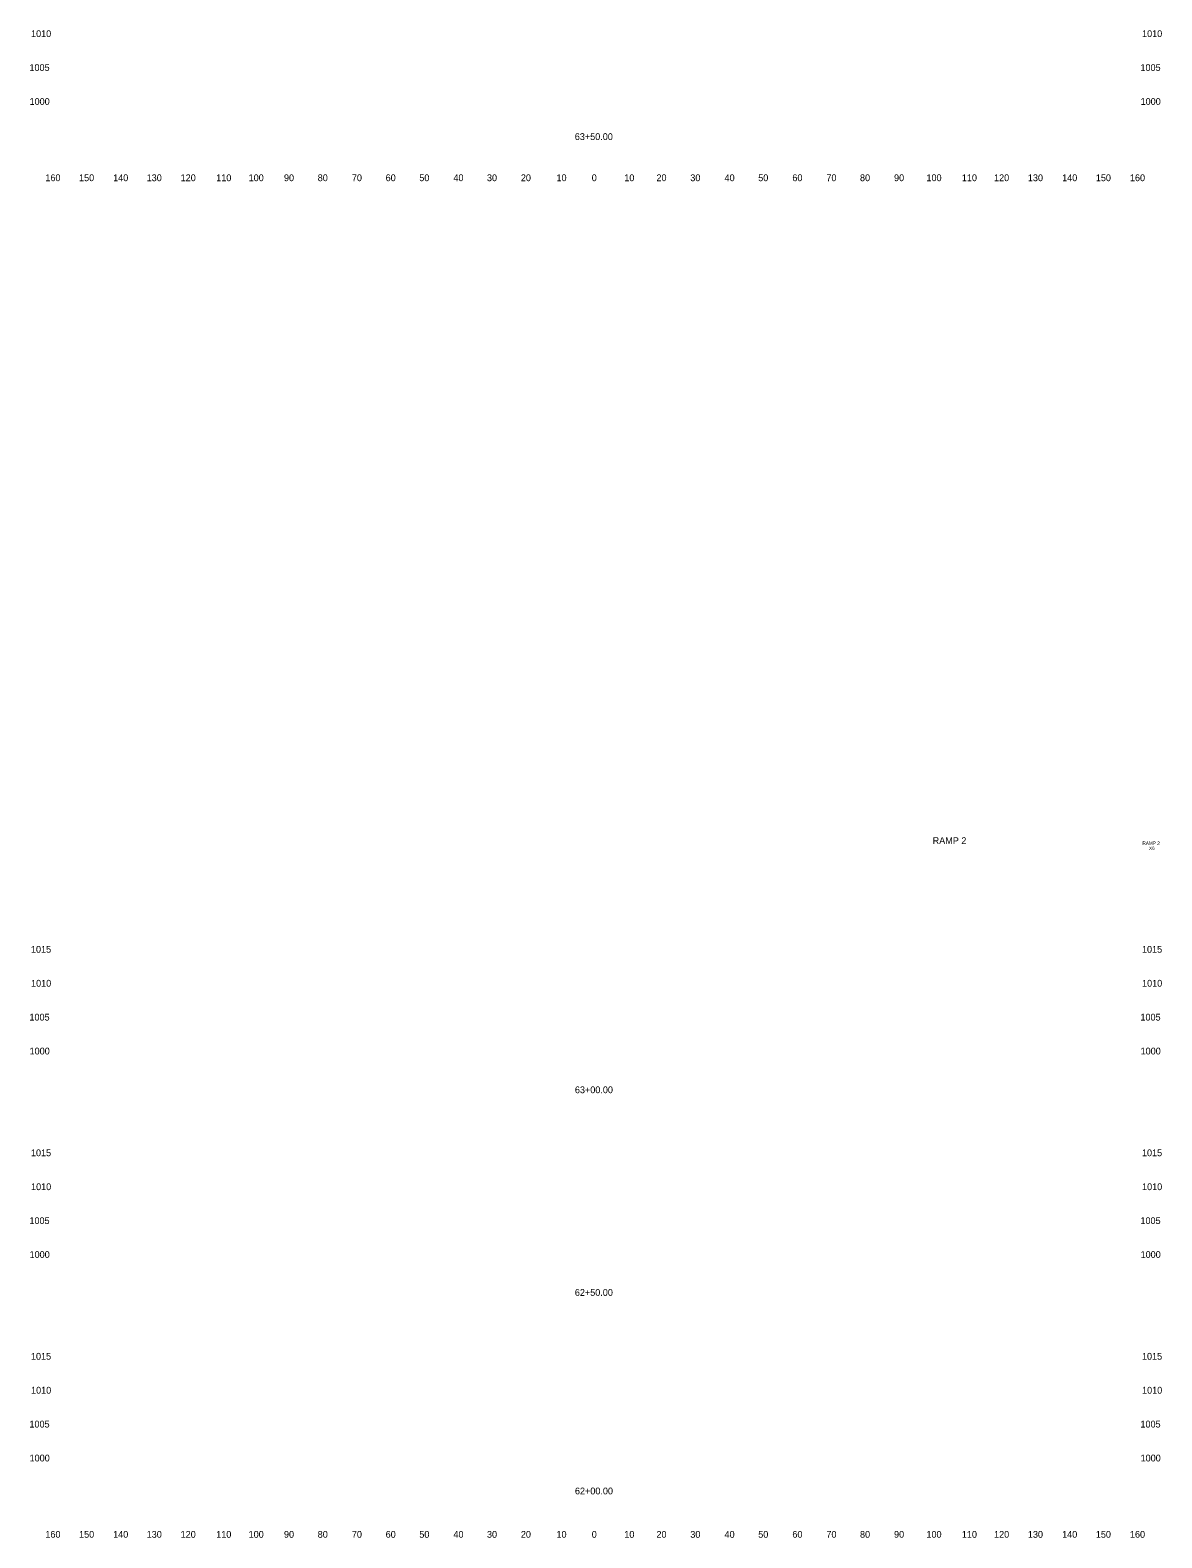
# Model space of a CAD drawing. Extents: x 4994 to 5328, y 4997 to 8804.
# Drawn here: x 4993.6 to 5327.5, y 6997.5 to 7442 of the extents above; entities that cross this region are included whole.
import ezdxf

# ---------------------------------------------------------------- set-up
doc = ezdxf.new("R2010")
doc.units = 0
for name, color, linetype in [('RD_SHT_ID', 7, 'Continuous'), ('RD_XS_TX_Offset', 7, 'Continuous'), ('RD_XS_TX_Station', 7, 'Continuous')]:
    doc.layers.add(name, color=color, linetype=linetype)

msp = doc.modelspace()

# ---------------------------------------------------------------- texts
at = {"layer": 'RD_SHT_ID'}
for s, height, p in [('RAMP 2', 2, (5259.89, 7202.06)), ('RAMP 2', 1, (5321.78, 7201.8)), ('X6', 1, (5323.71, 7200.3))]:
    msp.add_text(s, height=height, dxfattribs=at).set_placement(p)
at = {"layer": 'RD_XS_TX_Offset'}
for s, p in [('1010', (4993.88, 7440)), ('1010', (5321.68, 7440)), ('1005', (4993.4, 7430)), ('1005', (5321.2, 7430)), ('1000', (4993.44, 7420)), ('1000', (5321.24, 7420)), ('160', (4998.1, 7397.5)), ('150', (5008.04, 7397.5)), ('140', (5018.1, 7397.5)), ('130', (5027.99, 7397.5)), ('120', (5038.01, 7397.5)), ('110', (5048.51, 7397.5)), ('100', (5058.07, 7397.5)), ('90', (5068.5, 7397.5)), ('80', (5078.46, 7397.5)), ('70', (5088.54, 7397.5)), ('60', (5098.5, 7397.5)), ('50', (5108.43, 7397.5)), ('40', (5118.5, 7397.5)), ('30', (5128.39, 7397.5)), ('20', (5138.4, 7397.5)), ('10', (5148.91, 7397.5)), ('0', (5159.3, 7397.5)), ('0', (5159.3, 7397.5)), ('10', (5168.91, 7397.5)), ('20', (5178.4, 7397.5)), ('30', (5188.39, 7397.5)), ('40', (5198.5, 7397.5)), ('50', (5208.43, 7397.5)), ('60', (5218.5, 7397.5)), ('70', (5228.54, 7397.5)), ('80', (5238.46, 7397.5)), ('90', (5248.5, 7397.5)), ('100', (5258.07, 7397.5)), ('110', (5268.51, 7397.5)), ('120', (5278.01, 7397.5)), ('130', (5287.99, 7397.5)), ('140', (5298.1, 7397.5)), ('150', (5308.04, 7397.5)), ('160', (5318.1, 7397.5)), ('1015', (4993.85, 7170)), ('1015', (5321.65, 7170)), ('1010', (4993.88, 7160)), ('1010', (5321.68, 7160)), ('1005', (4993.4, 7150)), ('1005', (5321.2, 7150)), ('1000', (4993.44, 7140)), ('1000', (5321.24, 7140)), ('1015', (4993.85, 7110)), ('1015', (5321.65, 7110)), ('1010', (4993.88, 7100)), ('1010', (5321.68, 7100)), ('1005', (4993.4, 7090)), ('1005', (5321.2, 7090)), ('1000', (4993.44, 7080)), ('1000', (5321.24, 7080)), ('1015', (4993.85, 7050)), ('1015', (5321.65, 7050)), ('1010', (4993.88, 7040)), ('1010', (5321.68, 7040)), ('1005', (4993.4, 7030)), ('1005', (5321.2, 7030)), ('1000', (4993.44, 7020)), ('1000', (5321.24, 7020)), ('160', (4998.1, 6997.5)), ('150', (5008.04, 6997.5)), ('140', (5018.1, 6997.5)), ('130', (5027.99, 6997.5)), ('120', (5038.01, 6997.5)), ('110', (5048.51, 6997.5)), ('100', (5058.07, 6997.5)), ('90', (5068.5, 6997.5)), ('80', (5078.46, 6997.5)), ('70', (5088.54, 6997.5)), ('60', (5098.5, 6997.5)), ('50', (5108.43, 6997.5)), ('40', (5118.5, 6997.5)), ('30', (5128.39, 6997.5)), ('20', (5138.4, 6997.5)), ('10', (5148.91, 6997.5)), ('0', (5159.3, 6997.5)), ('0', (5159.3, 6997.5)), ('10', (5168.91, 6997.5)), ('20', (5178.4, 6997.5)), ('30', (5188.39, 6997.5)), ('40', (5198.5, 6997.5)), ('50', (5208.43, 6997.5)), ('60', (5218.5, 6997.5)), ('70', (5228.54, 6997.5)), ('80', (5238.46, 6997.5)), ('90', (5248.5, 6997.5)), ('100', (5258.07, 6997.5)), ('110', (5268.51, 6997.5)), ('120', (5278.01, 6997.5)), ('130', (5287.99, 6997.5)), ('140', (5298.1, 6997.5)), ('150', (5308.04, 6997.5)), ('160', (5318.1, 6997.5))]:
    msp.add_text(s, height=2, dxfattribs=at).set_placement(p)
at = {"layer": 'RD_XS_TX_Station'}
for s, p in [('63+50.00', (5154.31, 7409.64)), ('63+00.00', (5154.34, 7128.58)), ('62+50.00', (5154.32, 7068.82)), ('62+00.00', (5154.35, 7010.29))]:
    msp.add_text(s, height=2, dxfattribs=at).set_placement(p)

doc.saveas('drawing.dxf')
